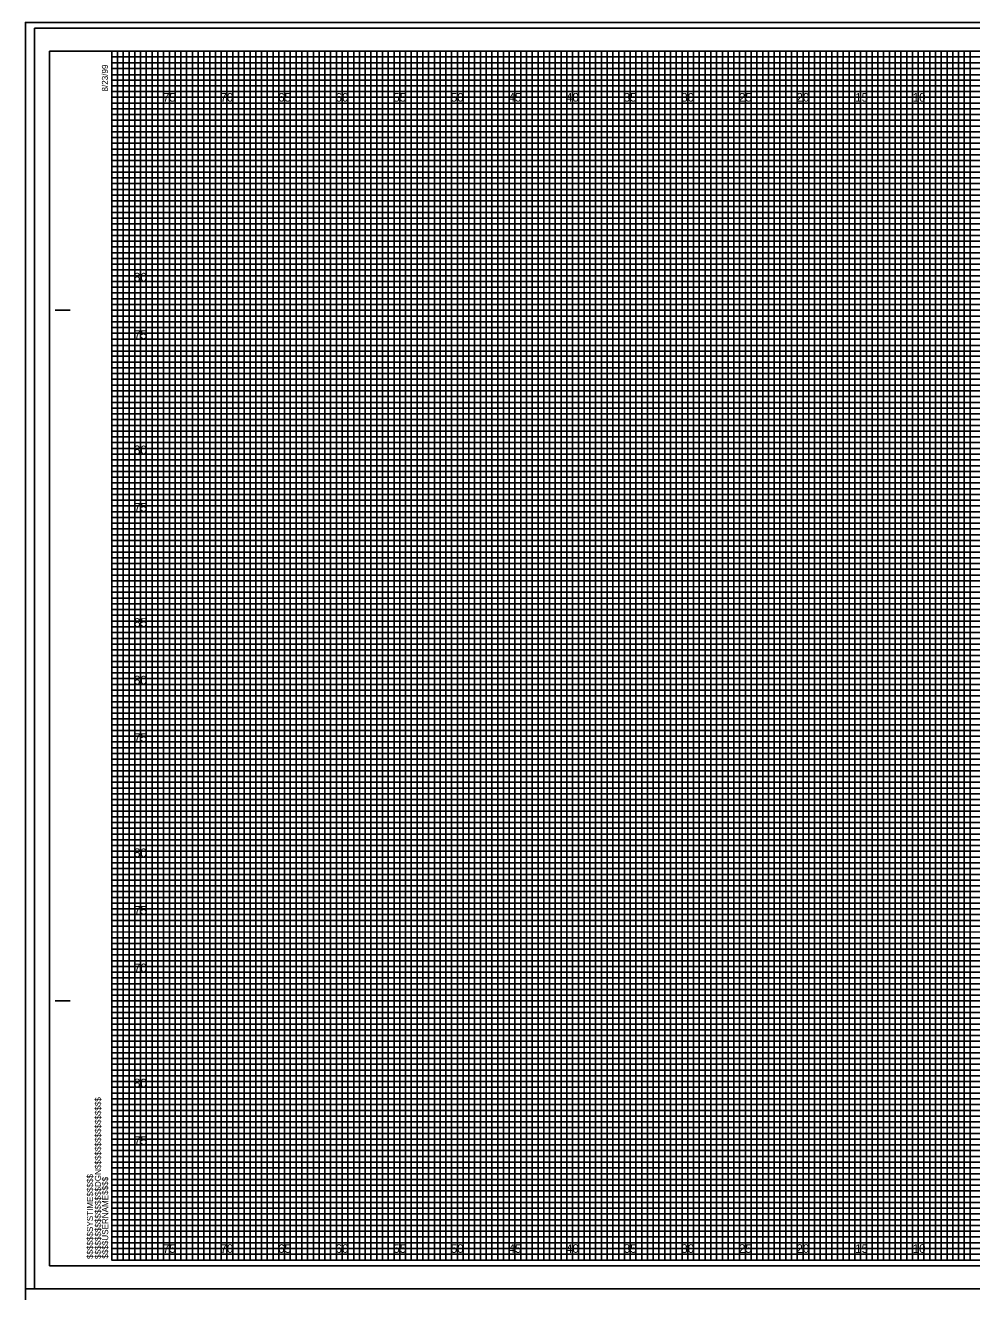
# Model space of a CAD drawing. Extents: x -8 to 533, y -20 to 768.
# Drawn here: x -7.5 to 74.6, y 327.2 to 437.2 of the extents above; entities that cross this region are included whole.
import ezdxf

# ---------------------------------------------------------------- set-up
doc = ezdxf.new("R2010")
doc.units = 0
for name, color, linetype in [('Prop XS Elevation Labels', 7, 'Continuous'), ('Prop XS Offset Labels', 7, 'Continuous'), ('Sheet Cross Section CELL', 7, 'Continuous'), ('Sheet Cross Section Grid Major CELL', 7, 'Continuous'), ('Sheet Cross Section Grid Middle CELL', 7, 'Continuous'), ('Sheet Cross Section Grid Minor 1 CELL', 7, 'Continuous'), ('Sheet Cross Section Grid Minor 2 CELL', 7, 'Continuous'), ('Sheet Cutting Line CELL', 7, 'Continuous'), ('Sheet DOT Grid CELL', 7, 'Continuous'), ('Sheet Plot Border Inside CELL', 7, 'Continuous'), ('Sheet Plot Border Outside CELL', 7, 'Continuous'), ('WEI Plot Border', 7, 'Continuous')]:
    doc.layers.add(name, color=color, linetype=linetype)

msp = doc.modelspace()

# ---------------------------------------------------------------- linework, layer by layer
at = {"layer": 'Sheet Cross Section CELL'}
for p, q in [((-4.9, 412.5), (-3.65, 412.5)), ((-4.85, 412.5), (-3.6, 412.5)), ((-4.9, 352.5), (-3.65, 352.5)), ((-4.85, 352.5), (-3.6, 352.5)), ((0, 330), (0, 330)), ((0, 330), (0, 330)), ((0, 330), (0, 330)), ((0, 330), (0, 330)), ((0, 330), (0, 330)), ((0, 330), (0, 330)), ((0, 330), (0, 330))]:
    msp.add_line(p, q, dxfattribs=at)
msp.add_lwpolyline([(160, 435), (0, 435), (0, 330), (160, 330)], close=True, dxfattribs=at)
at = {"layer": 'Sheet Cross Section Grid Major CELL'}
for p, q in [((5, 435), (0, 435)), ((5, 330), (5, 435)), ((15, 435), (10, 435)), ((10, 435), (10, 330)), ((15, 330), (15, 435)), ((25, 435), (20, 435)), ((20, 435), (20, 330)), ((25, 330), (25, 435)), ((35, 435), (30, 435)), ((30, 435), (30, 330)), ((35, 330), (35, 435)), ((45, 435), (40, 435)), ((40, 435), (40, 330)), ((45, 330), (45, 435)), ((55, 435), (50, 435)), ((50, 435), (50, 330)), ((55, 330), (55, 435)), ((65, 435), (60, 435)), ((60, 435), (60, 330)), ((65, 330), (65, 435)), ((75, 435), (70, 435)), ((70, 435), (70, 330)), ((10, 330), (5, 330)), ((20, 330), (15, 330)), ((30, 330), (25, 330)), ((40, 330), (35, 330)), ((50, 330), (45, 330)), ((60, 330), (55, 330)), ((70, 330), (65, 330))]:
    msp.add_line(p, q, dxfattribs=at)
for points in [[(0, 430), (160, 430), (160, 425), (0, 425)], [(0, 420), (160, 420), (160, 415), (0, 415)], [(0, 410), (160, 410), (160, 405), (0, 405)], [(0, 400), (160, 400), (160, 395), (0, 395)], [(0, 390), (160, 390), (160, 385), (0, 385)], [(0, 380), (160, 380), (160, 375), (0, 375)], [(0, 370), (160, 370), (160, 365), (0, 365)], [(0, 360), (160, 360), (160, 355), (0, 355)], [(0, 350), (160, 350), (160, 345), (0, 345)], [(0, 340), (160, 340), (160, 335), (0, 335)]]:
    msp.add_lwpolyline(points, dxfattribs=at)
at = {"layer": 'Sheet Cross Section Grid Middle CELL'}
for points in [[(0, 435), (2.5, 435), (2.5, 330), (7.5, 330), (7.5, 435), (12.5, 435), (12.5, 330), (17.5, 330), (17.5, 435), (22.5, 435), (22.5, 330), (27.5, 330), (27.5, 435), (32.5, 435), (32.5, 330), (37.5, 330), (37.5, 435), (42.5, 435), (42.5, 330), (47.5, 330), (47.5, 435), (52.5, 435), (52.5, 330), (57.5, 330), (57.5, 435), (62.5, 435), (62.5, 330), (67.5, 330), (67.5, 435), (72.5, 435), (72.5, 330), (77.5, 330)], [(0, 432.5), (137.5, 432.5)], [(0, 422.5), (160, 422.5), (160, 427.5), (0, 427.5)], [(0, 412.5), (160, 412.5), (160, 417.5), (0, 417.5)], [(0, 402.5), (160, 402.5), (160, 407.5), (0, 407.5)], [(0, 392.5), (160, 392.5), (160, 397.5), (0, 397.5)], [(0, 382.5), (160, 382.5), (160, 387.5), (0, 387.5)], [(0, 372.5), (160, 372.5), (160, 377.5), (0, 377.5)], [(0, 362.5), (160, 362.5), (160, 367.5), (0, 367.5)], [(0, 352.5), (160, 352.5), (160, 357.5), (0, 357.5)], [(0, 342.5), (160, 342.5), (160, 347.5), (0, 347.5)], [(0, 332.5), (160, 332.5), (160, 337.5), (0, 337.5)]]:
    msp.add_lwpolyline(points, dxfattribs=at)
at = {"layer": 'Sheet Cross Section Grid Minor 1 CELL'}
for p, q in [((0, 434.5), (130, 434.5)), ((130, 433.99), (0, 433.99)), ((0, 433.99), (0, 433.5)), ((0, 433.5), (130, 433.5)), ((130, 432.94), (0, 432.94)), ((0, 432.94), (0, 432)), ((0, 432), (160, 432))]:
    msp.add_line(p, q, dxfattribs=at)
for points in [[(0, 431.5), (135, 431.5), (160, 431.5), (160, 431), (0, 431)], [(0, 430.5), (160, 430.5), (160, 429.5), (0, 429.5)], [(0, 429), (160, 429), (160, 428.5), (0, 428.49)], [(0, 428), (160, 428), (160, 427), (0, 427)], [(0, 426.5), (160, 426.5), (160, 426), (0, 426)], [(0, 425.5), (160, 425.5), (160, 424.5), (0, 424.5)], [(0, 424), (160, 424), (160, 423.5), (0, 423.5)], [(0, 423), (160, 423), (160, 422), (0, 422)], [(0, 421.5), (160, 421.5), (160, 421), (0, 421)], [(0, 420.5), (160, 420.5), (160, 419.5), (0, 419.5)], [(0, 419), (160, 419), (160, 418.5), (0, 418.5)], [(0, 418), (160, 418), (160, 416.98), (160, 416.5), (160, 416), (0, 416)], [(0, 417), (160, 417), (160, 416.5), (0, 416.5)], [(0, 415.5), (160, 415.5), (160, 414.5), (0, 414.51)], [(0, 414.51), (160, 414.5), (160, 414), (0, 414)], [(0, 413.5), (160, 413.5), (160, 413), (0, 413)], [(0, 412), (160, 412), (160, 411.5), (0, 411.5)], [(0, 411), (160, 411), (160, 410.5), (0, 410.5)], [(-0.04, 409.44), (160, 409.44), (160, 408.94), (-0.04, 408.94)], [(0, 408.5), (160, 408.5), (160, 408), (0, 408)], [(0, 407), (160, 407), (160, 406.5), (0, 406.5)], [(0, 406), (160, 406), (160, 405.5), (0, 405.5)], [(0, 404.5), (160, 404.5), (160, 404), (0, 404)], [(0, 403.5), (160, 403.5), (160, 403), (0, 403)], [(0, 402), (160, 402), (160, 401.5), (0, 401.5)], [(0, 401), (160, 401), (160, 400.5), (0, 400.5)], [(0, 399.5), (160, 399.5), (160, 398.99), (0, 399)], [(0, 398.5), (160, 398.5), (160, 398), (0, 398)], [(0, 397), (160, 397), (160, 396.5), (0, 396.5)], [(0, 396), (160, 396), (160, 395.5), (0, 395.5)], [(0, 394.5), (160, 394.5), (160, 394), (0, 394)], [(0, 393.5), (160, 393.5), (160, 393), (0, 393)], [(0, 392), (160, 392), (160, 391.5), (0, 391.5)], [(0, 391), (160, 391), (160, 390.5), (0, 390.5)], [(0, 389.5), (160, 389.5), (160, 389), (0, 389)], [(0, 388.5), (160.03, 388.45), (160, 388), (0, 388)], [(0, 387), (160, 387), (160, 386.5), (0, 386.5)], [(0, 386), (160, 386), (160, 385.5), (0, 385.5)], [(0, 384.5), (160, 384.5), (160, 384), (0, 384)], [(0, 383.5), (160, 383.5), (160, 383), (0, 383)], [(0, 382), (160, 382), (160, 381.5), (0, 381.5)], [(0, 381), (160, 381), (160, 380.5), (0, 380.5)], [(0, 379.5), (160, 379.5), (160, 379), (0, 379)], [(0, 378.5), (160, 378.5), (160, 378), (0, 378)], [(0, 377), (160, 377), (160, 376.5), (0, 376.5)], [(0, 376), (160, 376), (160, 375.5), (0, 375.5)], [(0, 374.5), (160, 374.5), (160, 374), (0, 374)], [(0, 373.5), (160, 373.5), (160, 373), (0, 373)], [(0, 372), (160, 372), (160, 371.5), (0, 371.5)], [(0, 371), (160, 371), (160, 370.5), (0, 370.5)], [(0, 369.5), (160, 369.5), (160, 368.99), (0, 369)], [(0, 368.5), (160, 368.5), (160, 368), (0, 368)], [(0, 367), (160, 367), (160, 366.5), (0, 366.5)], [(0, 366), (160, 366), (160, 365.5), (0, 365.5)], [(0, 364.5), (160, 364.5), (160, 364), (0, 364)], [(0, 363.5), (160, 363.5), (160, 363), (0, 363)], [(0, 362), (160, 362), (160, 361.5), (0, 361.5)], [(0, 361), (160, 361), (160, 360.5), (0, 360.5)], [(0, 359.5), (160, 359.5), (160, 359), (0, 359)], [(0, 358.5), (160.03, 358.45), (160, 358), (0, 358)], [(0, 357), (160, 357), (160, 356.5), (0, 356.5)], [(0, 356), (160, 356), (160, 355.5), (0, 355.5)], [(0, 354.5), (160, 354.5), (160, 354), (0, 354)], [(0, 353.5), (160, 353.5), (160, 353), (0, 353)], [(0, 352), (160, 352), (160, 351.5), (0, 351.5)], [(0, 351), (160, 351), (160, 350.5), (0, 350.5)], [(0, 349.5), (160, 349.5), (160, 349), (0, 349)], [(0, 348.5), (160, 348.5), (160, 348), (0, 348)], [(0, 347), (160, 347), (160, 346.5), (0, 346.5)], [(0, 346), (160, 346), (160, 345.5), (0, 345.5)], [(0, 344.5), (160, 344.5), (160, 344), (0, 344)], [(0, 343.5), (160, 343.5), (160, 343), (0, 343)], [(0, 342), (160, 342), (160, 341.5), (0, 341.5)], [(0, 341), (160, 341), (160, 340.5), (0, 340.5)], [(0, 339.5), (160, 339.5), (160, 339), (0, 339)], [(0, 338.5), (160, 338.5), (160, 338), (0, 338)], [(0, 337), (160, 337), (160, 336.5), (0, 336.5)], [(0, 336), (160, 336), (160, 335.5), (0, 335.5)], [(0, 334.5), (160, 334.5), (160, 334), (0, 334)], [(0, 333.5), (160, 333.5), (160, 333), (0, 333)], [(0, 332), (160, 332), (160, 331.5), (0, 331.5)], [(0, 331), (160, 331), (160, 330.5), (0, 330.5)]]:
    msp.add_lwpolyline(points, dxfattribs=at)
at = {"layer": 'Sheet Cross Section Grid Minor 2 CELL'}
for points in [[(0, 330), (0.5, 330), (0.5, 435), (1, 435), (1, 330)], [(1, 330), (1.5, 330), (1.5, 435), (2, 435), (2, 330)], [(2.5, 330), (3, 330), (3, 435), (3.5, 435), (3.5, 330)], [(3.5, 330), (4, 330), (4, 435), (4.5, 435), (4.5, 330)], [(5, 330), (5.5, 330), (5.5, 435), (6, 435), (6, 330)], [(6, 330), (6.5, 330), (6.5, 435), (7, 435), (7, 330)], [(7.5, 330), (8, 330), (8, 435), (8.5, 435), (8.5, 330)], [(8.5, 330), (9, 330), (9, 435), (9.5, 435), (9.5, 330)], [(10, 330), (10.5, 330), (10.5, 435), (11, 435), (11, 330)], [(11, 330), (11.5, 330), (11.5, 435), (12, 435), (12, 330)], [(12.5, 330), (13, 330), (13, 435), (13.5, 435), (13.5, 330)], [(13.5, 330), (14, 330), (14, 435), (14.5, 435), (14.5, 330)], [(15, 330), (15.5, 330), (15.5, 435), (16, 435), (16, 330)], [(16, 330), (16.5, 330), (16.5, 435), (17, 435), (17, 330)], [(17.5, 330), (18, 330), (18, 435), (18.5, 435), (18.5, 330)], [(18.5, 330), (19, 330), (19, 435), (19.5, 435), (19.5, 330)], [(20, 330), (20.5, 330), (20.5, 435), (21, 435), (21, 330)], [(21, 330), (21.5, 330), (21.5, 435), (22, 435), (22, 330)], [(22.5, 330), (23, 330), (23, 435), (23.5, 435), (23.5, 330)], [(23.5, 330), (24, 330), (24, 435), (24.5, 435), (24.5, 330)], [(25, 330), (25.5, 330), (25.5, 435), (26, 435), (26, 330)], [(26, 330), (26.5, 330), (26.5, 435), (27, 435), (27, 330)], [(27.5, 330), (28, 330), (28, 435), (28.5, 435), (28.5, 330)], [(28.5, 330), (29, 330), (29, 435), (29.5, 435), (29.5, 330)], [(30, 330), (30.5, 330), (30.5, 435), (31, 435), (31, 330)], [(31, 330), (31.5, 330), (31.5, 435), (32, 435), (32, 330)], [(32.5, 330), (33, 330), (33, 435), (33.5, 435), (33.5, 330)], [(33.5, 330), (34, 330), (34, 435), (34.5, 435), (34.5, 330)], [(35, 330), (35.5, 330), (35.5, 435), (36, 435), (36, 330)], [(36, 330), (36.5, 330), (36.5, 435), (37, 435), (37, 330)], [(37.5, 330), (38, 330), (38, 435), (38.5, 435), (38.5, 330)], [(38.5, 330), (39, 330), (39, 435), (39.5, 435), (39.5, 330)], [(40, 330), (40.5, 330), (40.5, 435), (41, 435), (41, 330)], [(41, 330), (41.5, 330), (41.5, 435), (42, 435), (42, 330)], [(42.5, 330), (43, 330), (43, 435), (43.5, 435), (43.5, 330)], [(43.5, 330), (44, 330), (44, 435), (44.5, 435), (44.5, 330)], [(45, 330), (45.5, 330), (45.5, 435), (46, 435), (46, 330)], [(46, 330), (46.5, 330), (46.5, 435), (47, 435), (47, 330)], [(47.5, 330), (48, 330), (48, 435), (48.5, 435), (48.5, 330)], [(48.5, 330), (49, 330), (49, 435), (49.5, 435), (49.5, 330)], [(50, 330), (50.5, 330), (50.5, 435), (51, 435), (51, 330)], [(51, 330), (51.5, 330), (51.5, 435), (52, 435), (52, 330)], [(52.5, 330), (53, 330), (53, 435), (53.5, 435), (53.5, 330)], [(53.5, 330), (54, 330), (54, 435), (54.5, 435), (54.5, 330)], [(55, 330), (55.5, 330), (55.5, 435), (56, 435), (56, 330)], [(56, 330), (56.5, 330), (56.5, 435), (57, 435), (57, 330)], [(57.5, 330), (58, 330), (58, 435), (58.5, 435), (58.5, 330)], [(58.5, 330), (59, 330), (59, 435), (59.5, 435), (59.5, 330)], [(60, 330), (60.5, 330), (60.5, 435), (61, 435), (61, 330)], [(61, 330), (61.5, 330), (61.5, 435), (62, 435), (62, 330)], [(62.5, 330), (63, 330), (63, 435), (63.5, 435), (63.5, 330)], [(63.5, 330), (64, 330), (64, 435), (64.5, 435), (64.5, 330)], [(65, 330), (65.5, 330), (65.5, 435), (66, 435), (66, 330)], [(66, 330), (66.5, 330), (66.5, 435), (67, 435), (67, 330)], [(67.5, 330), (68, 330), (68, 435), (68.5, 435), (68.5, 330)], [(68.5, 330), (69, 330), (69, 435), (69.5, 435), (69.5, 330)], [(70, 330), (70.5, 330), (70.5, 435), (71, 435), (71, 330)], [(71, 330), (71.5, 330), (71.5, 435), (72, 435), (72, 330)], [(72.5, 330), (73, 330), (73, 435), (73.5, 435), (73.5, 330)], [(73.5, 330), (74, 330), (74, 435), (74.5, 435), (74.5, 330)]]:
    msp.add_lwpolyline(points, dxfattribs=at)
at = {"layer": 'Sheet Cutting Line CELL'}
for p, q in [((161.65, 437), (-6.7, 437)), ((-6.7, 437), (-6.7, 327.5)), ((-6.7, 327.5), (161.65, 327.5))]:
    msp.add_line(p, q, dxfattribs=at)
at = {"layer": 'Sheet DOT Grid CELL'}
for p, q in [((5, 330), (5, 435)), ((10, 330), (10, 435)), ((15, 330), (15, 435)), ((20, 330), (20, 435)), ((25, 330), (25, 435)), ((30, 330), (30, 435)), ((35, 330), (35, 435)), ((40, 330), (40, 435)), ((45, 330), (45, 435)), ((50, 330), (50, 435)), ((55, 330), (55, 435)), ((60, 330), (60, 435)), ((65, 330), (65, 435)), ((70, 330), (70, 435)), ((0, 430), (160, 430)), ((0, 425), (160, 425)), ((0, 420), (160, 420)), ((0, 415), (160, 415)), ((0, 410), (160, 410)), ((0, 405), (160, 405)), ((0, 400), (160, 400)), ((0, 395), (160, 395)), ((0, 390), (160, 390)), ((0, 385), (160, 385)), ((0, 380), (160, 380)), ((0, 375), (160, 375)), ((0, 370), (160, 370)), ((0, 365), (160, 365)), ((0, 360), (160, 360)), ((0, 355), (160, 355)), ((0, 350), (160, 350)), ((0, 345), (160, 345)), ((0, 340), (160, 340)), ((0, 335), (160, 335))]:
    msp.add_line(p, q, dxfattribs=at)
at = {"layer": 'Sheet Plot Border Inside CELL'}
msp.add_lwpolyline([(-5.4, 329.5), (161.2, 329.5), (161.2, 435), (-5.4, 435)], close=True, dxfattribs=at)
at = {"layer": 'Sheet Plot Border Outside CELL'}
msp.add_lwpolyline([(-6.7, 327.5), (161.65, 327.5), (161.65, 437), (-6.7, 437)], close=True, dxfattribs=at)
at = {"layer": 'WEI Plot Border'}
for points in [[(-7.5, 327.5), (162.5, 327.5), (162.5, 437.5), (-7.5, 437.5)], [(-7.5, 217.5), (162.5, 217.5), (162.5, 327.5), (-7.5, 327.5)]]:
    msp.add_lwpolyline(points, close=True, dxfattribs=at)

# ---------------------------------------------------------------- texts
at = {"layer": 'Prop XS Elevation Labels'}
for s, p in [('80', (1.93, 415)), ('75', (1.94, 410)), ('80', (1.93, 400)), ('75', (1.94, 395)), ('85', (1.94, 385)), ('80', (1.93, 380)), ('75', (1.94, 375)), ('80', (1.93, 365)), ('75', (1.94, 360)), ('70', (1.93, 355)), ('80', (1.93, 345)), ('75', (1.94, 340))]:
    msp.add_text(s, height=0.75, dxfattribs=at).set_placement(p)
at = {"layer": 'Prop XS Offset Labels'}
for s, p in [('75', (4.44, 430.62)), ('70', (9.43, 430.62)), ('65', (14.44, 430.62)), ('60', (19.43, 430.62)), ('55', (24.44, 430.62)), ('50', (29.43, 430.62)), ('45', (34.44, 430.62)), ('40', (39.43, 430.62)), ('35', (44.44, 430.62)), ('30', (49.43, 430.62)), ('25', (54.44, 430.62)), ('20', (59.43, 430.62)), ('15', (64.53, 430.62)), ('10', (69.52, 430.62)), ('75', (4.44, 330.62)), ('70', (9.43, 330.62)), ('65', (14.44, 330.62)), ('60', (19.43, 330.62)), ('55', (24.44, 330.62)), ('50', (29.43, 330.62)), ('45', (34.44, 330.62)), ('40', (39.43, 330.62)), ('35', (44.44, 330.62)), ('30', (49.43, 330.62)), ('25', (54.44, 330.62)), ('20', (59.43, 330.62)), ('15', (64.53, 330.62)), ('10', (69.52, 330.62))]:
    msp.add_text(s, height=0.75, dxfattribs=at).set_placement(p)
at = {"layer": 'Sheet Cross Section CELL'}
for s, p in [('8/23/99', (-0.33, 431.5)), ('$$$$$$$$$$$$$$$$DGN$$$$$$$$$$$$$$$$', (-0.94, 330.09)), ('$$$$$$SYSTIME$$$$$', (-1.63, 330.09)), ('$$$$USERNAME$$$$', (-0.31, 330.12))]:
    msp.add_text(s, height=0.525, rotation=90, dxfattribs=at).set_placement(p)

doc.saveas('drawing.dxf')
